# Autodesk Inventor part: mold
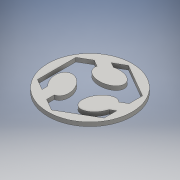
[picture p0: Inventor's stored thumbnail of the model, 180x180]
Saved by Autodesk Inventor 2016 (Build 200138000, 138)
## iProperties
Created: 2015-06
Part Number: mold
Material: Generic
Document SubType Name: Modeling
Designer: Mohamed
Density: 1 g/cm^3
Appearance: Default
Author: Mohamed
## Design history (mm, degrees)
sketch "Sketch1"
  geometry: L1 (278.503, -324.566)-(278.503, -324.249); L2 (278.503, -324.249)-(278.503, -323.98); L3 (278.503, -323.98)-(278.503, -323.712); L4 (278.503, -323.712)-(278.501, -320.016); L5 (278.501, -320.016)-(278.482, -316.319); L6 (278.482, -316.319)-(278.512, -312.624); L7 (278.512, -312.624)-(278.518, -311.914); L8 (278.518, -311.914)-(278.305, -311.38); L9 (278.305, -311.38)-(277.877, -310.825); L10 (277.877, -310.825)-(274.184, -306.037); L11 (274.184, -306.037)-(271.646, -300.705); L12 (271.646, -300.705)-(270.618, -294.726); L13 (270.618, -294.726)-(269.912, -290.617); L14 (269.912, -290.617)-(269.91, -286.515); L15 (269.91, -286.515)-(271.404, -282.536); L16 (271.404, -282.536)-(272.734, -278.992); L17 (272.734, -278.992)-(274.984, -276.278); L18 (274.984, -276.278)-(278.582, -274.855); L19 (278.582, -274.855)-(281.479, -273.71); L20 (281.479, -273.71)-(284.431, -273.782); L21 (284.431, -273.782)-(287.397, -274.574); L22 (287.397, -274.574)-(291.278, -275.61); L23 (291.278, -275.61)-(294.61, -277.652); L24 (294.61, -277.652)-(297.558, -280.313); L25 (297.558, -280.313)-(303.288, -285.487); L26 (303.288, -285.487)-(307.05, -291.866); L27 (307.05, -291.866)-(308.893, -299.355); L28 (308.893, -299.355)-(309.831, -303.17); L29 (309.831, -303.17)-(310.076, -307.034); L30 (310.076, -307.034)-(309.228, -310.909); L31 (309.228, -310.909)-(308.448, -314.475); L32 (308.448, -314.475)-(306.851, -317.556); L33 (306.851, -317.556)-(303.816, -319.749); L34 (303.816, -319.749)-(303.216, -320.183); L35 (303.216, -320.183)-(302.592, -320.585); L36 (302.592, -320.585)-(301.904, -320.858); L37 (301.904, -320.858)-(301.474, -321.029); L38 (301.474, -321.029)-(301.29, -321.29); L39 (301.29, -321.29)-(301.339, -321.741); L40 (301.339, -321.741)-(301.356, -321.895); L41 (301.356, -321.895)-(301.342, -322.052); L42 (301.342, -322.052)-(301.342, -322.208); L43 (301.342, -322.208)-(301.341, -327.109); L44 (301.341, -327.109)-(301.362, -332.012); L45 (301.362, -332.012)-(301.321, -336.914); L46 (301.321, -336.914)-(301.314, -337.724); L47 (301.314, -337.724)-(301.572, -338.175); L48 (301.572, -338.175)-(302.265, -338.568); L49 (302.265, -338.568)-(306.658, -341.062); L50 (306.658, -341.062)-(311.02, -343.61); L51 (311.02, -343.61)-(315.417, -346.097); L52 (315.417, -346.097)-(316.156, -346.515); L53 (316.156, -346.515)-(316.45, -346.991); L54 (316.45, -346.991)-(316.419, -347.842); L55 (316.419, -347.842)-(316.355, -349.59); L56 (316.355, -349.59)-(316.409, -351.343); L57 (316.409, -351.343)-(316.394, -353.094); L58 (316.394, -353.094)-(316.387, -353.985); L59 (316.387, -353.985)-(316.366, -354.022); L60 (316.366, -354.022)-(315.465, -353.98); L61 (315.465, -353.98)-(312.942, -353.865); L62 (312.942, -353.865)-(310.426, -353.642); L63 (310.426, -353.642)-(307.928, -353.264); L64 (307.928, -353.264)-(300.064, -352.072)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; 1 further point
  constraints: 3 other
extrude "Extrusion1" new body sketch "Sketch1" distance "d0" = 10; taper "d1" = 0 deg
sketch "Sketch3"
  geometry: L1 (0.533, 108.871)-(347.667, 108.871); L2 (347.667, 108.871)-(347.667, -29.221); L3 (347.667, -29.221)-(0.533, -29.221); L4 (0.533, -29.221)-(0.533, 108.871); L5 (54.028, 103.645)-(95.891, 79.475); L6 (95.891, 31.136)-(54.028, 6.967); L7 (12.165, 31.136)-(12.165, 79.475); L8 (40.338, 95.741)-(46.428, 92.224); L9 (26.749, 87.895)-(35.009, 83.127); L10 (12.165, 79.475)-(26.749, 87.895); L11 (40.338, 95.741)-(54.028, 103.645); L12 (39.444, 15.387)-(39.444, 24.924); L13 (25.855, 23.232)-(25.855, 30.265); L14 (95.891, 62.635)-(87.632, 57.866); L15 (95.891, 46.944)-(89.8, 43.428); L16 (54.028, 6.967)-(39.444, 15.387); L17 (25.855, 23.232)-(12.165, 31.136); L18 (95.891, 79.475)-(95.891, 62.635); L19 (95.891, 46.944)-(95.891, 31.136); C1 r 52.771 at (54.028, 55.306); 5 further points; 4 other entities
  constraints: 30 end point, 1 centre point, 1 coincident, 1 parallel, 46 other
  dimensions: "d27" = 360 deg dimension on C1.centre point (53.149, 80.637) (derived)
extrude "Extrusion2" join sketch "Sketch3" distance "d31" = 5; taper "d32" = 0 deg
body "Solid1"
node "Image1"
